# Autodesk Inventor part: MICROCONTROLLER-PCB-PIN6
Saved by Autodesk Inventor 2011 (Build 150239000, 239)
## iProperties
Created: 2007-09
Part Number: MICROCONTROLLER-PCB-PIN6
Document SubType Name: Modeling
Density: 1 g/cm^3
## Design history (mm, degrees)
feature "Base1"
body "Solid1"
